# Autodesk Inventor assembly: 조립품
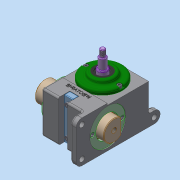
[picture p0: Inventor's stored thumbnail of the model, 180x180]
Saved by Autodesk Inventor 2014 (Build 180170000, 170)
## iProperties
Created: 2023-09
Part Number: 조립품
Document SubType Name: Assembly
Designer: dg
Author: dg
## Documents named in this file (11)
- C:\Users\dg\Desktop\730906V1008\조립품.iam
- C:\Users\dg\Desktop\730906V1008\본체.ipt
- C:\Users\dg\Desktop\730906V1008\가이드 부시.ipt
- C:\Users\dg\Desktop\730906V1008\래크.ipt
- C:\Users\dg\Desktop\730906V1008\베어링 6003.ipt
- C:\Users\dg\Desktop\730906V1008\볼트 M4.ipt
- C:\Users\dg\Desktop\730906V1008\부시 커버.ipt
- C:\Users\dg\Desktop\730906V1008\스톱퍼.ipt
- C:\Users\dg\Desktop\730906V1008\앞커버.ipt
- C:\Users\dg\Desktop\730906V1008\오일 실 17 30 5.ipt
- C:\Users\dg\Desktop\730906V1008\피니언.ipt
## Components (3 placed, 2 different names)
1. 가이드 부시:1
2. 가이드 부시:2
3. 피니언:1
